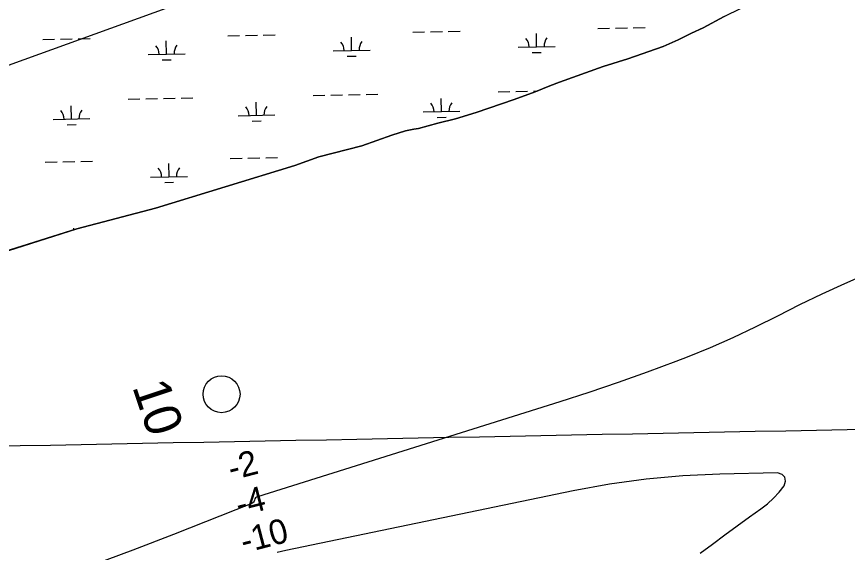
# Model space of a CAD drawing. Extents: x 3989314 to 4027622, y 243956 to 270014.
# Drawn here: x 3994901 to 3997154, y 255194 to 256648 of the extents above; entities that cross this region are included whole.
import ezdxf

# ---------------------------------------------------------------- set-up
doc = ezdxf.new("R2010")
doc.units = 0
for name, color, linetype in [('V-GRID-MAJR', 7, 'Continuous'), ('V-RIVR-EDGE', 7, 'Continuous'), ('V-RIVR-IDEN', 7, 'Continuous'), ('V-RIVR-MILE', 7, 'Continuous'), ('V-RIVR-RANG', 7, 'Continuous'), ('V-TOPO-MINR', 7, 'Continuous'), ('V-UTIL-LINE', 7, 'Continuous'), ('V-WETL-SWMP', 7, 'Continuous')]:
    doc.layers.add(name, color=color, linetype=linetype)

msp = doc.modelspace()

# ---------------------------------------------------------------- linework, layer by layer
at = {"layer": 'V-GRID-MAJR'}
msp.add_spline([(3993497.6, 255455.7), (3998815.3, 255559.8), (4004133, 255664.6), (4009450.7, 255770.2), (4014768.4, 255876.5), (4020086, 255983.7), (4025403.7, 256091.6)], degree=3, dxfattribs=at)
at = {"layer": 'V-RIVR-EDGE'}
msp.add_lwpolyline([(3994836.5, 255999.7), (3995064.6, 256071.4), (3995278, 256127.7), (3995655.8, 256243.8), (3995720.3, 256266.9), (3995837.6, 256297.4), (3995918.5, 256325.7), (3995955.7, 256337.7), (3995978.1, 256342.4), (3995990.7, 256344.3), (3996043.6, 256358.4), (3996091.8, 256370), (3996147.6, 256387), (3996250.8, 256422.5), (3996307.8, 256443.5), (3996346.8, 256459.8), (3996373.6, 256469.4), (3996492.1, 256512.3), (3996559, 256532.8), (3996654.2, 256566.6), (3996695, 256584.7), (3996731.4, 256602.8), (3996763.1, 256617.6), (3996820.4, 256647.6), (3996866.5, 256670.4)], dxfattribs=at)
at = {"layer": 'V-RIVR-MILE'}
msp.add_circle((3995456.9, 255622.8), 50, dxfattribs=at)
at = {"layer": 'V-TOPO-MINR'}
for points in [[(3997208.3, 255949.4), (3997146.5, 255922.7), (3997085.2, 255894.8), (3997024.6, 255865.4), (3996964.6, 255835), (3996904.4, 255804.7), (3996843.6, 255775.9), (3996781.9, 255749.2), (3996719.5, 255723.8), (3996689.3, 255712.1), (3996611.1, 255682.7), (3996532.6, 255654.4), (3996453.4, 255627.6), (3996374, 255601.8), (3995554, 255344.7), (3995551.2, 255343.2), (3995548.9, 255341.4), (3995547.4, 255338.8), (3995546.3, 255335.4), (3995545.3, 255332.6), (3995543.9, 255330.1), (3995541.8, 255328.2), (3995539.2, 255326.6), (3995326.4, 255242.5), (3995216.6, 255200.1), (3995106.4, 255159)], [(3996755.4, 255191.2), (3996788.6, 255216.2), (3996821.9, 255241), (3996855.4, 255265.5), (3996889.1, 255289.8), (3996920, 255312), (3996937.5, 255325.8), (3996954.1, 255340.7), (3996969.2, 255357.1), (3996983.2, 255374.5), (3996986.3, 255387.3), (3996985, 255397.9), (3996977.1, 255405), (3996964.8, 255409.8), (3996808.5, 255406.3), (3996708.2, 255401.3), (3996608.3, 255392.6), (3996509, 255378.5), (3996410.1, 255360.8), (3995631.1, 255198.8), (3995607.7, 255193.4)]]:
    msp.add_lwpolyline(points, dxfattribs=at)
at = {"layer": 'V-UTIL-LINE'}
msp.add_lwpolyline([(4011371.2, 261859.1), (4011335.1, 261835.4), (4010585.7, 261810.1), (4009561, 261669.6), (4009556.2, 261668.8), (4009323.1, 261637.1), (4006559.3, 260668.5), (4004279, 259872), (3996043.1, 256937.7), (3993486.8, 256012.2)], dxfattribs=at)
at = {"layer": 'V-WETL-SWMP'}
for p, q in [((3996820.4, 256647.6), (3996763.1, 256617.6)), ((3996525.5, 256616.5), (3996557.5, 256617.1)), ((3996573.5, 256617.4), (3996605.5, 256618)), ((3996763.1, 256617.6), (3996731.4, 256602.8)), ((3995473.9, 256595.5), (3995505.9, 256596.1)), ((3995521.9, 256596.5), (3995553.9, 256597.1)), ((3995569.8, 256597.4), (3995601.8, 256598)), ((3995975.7, 256605.5), (3996007.7, 256606.1)), ((3996023.7, 256606.5), (3996055.7, 256607.1)), ((3996071.7, 256607.4), (3996103.6, 256608)), ((3996311.4, 256565.7), (3996310.7, 256601.7)), ((3996477.5, 256615.5), (3996509.5, 256616.1)), ((3996731.4, 256602.8), (3996695, 256584.7)), ((3994972.1, 256585.5), (3995004.1, 256586.1)), ((3995020, 256586.5), (3995052, 256587.1)), ((3995068, 256587.4), (3995100, 256588)), ((3995307.8, 256545.7), (3995307, 256581.7)), ((3995809.6, 256555.7), (3995808.9, 256591.7)), ((3996695, 256584.7), (3996654.2, 256566.6)), ((3995759.6, 256554.8), (3995859.6, 256556.7)), ((3996261.4, 256564.8), (3996361.4, 256566.7)), ((3996299.7, 256550.1), (3996323.7, 256550.6)), ((3996654.2, 256566.6), (3996559, 256532.8)), ((3995257.8, 256544.8), (3995357.8, 256546.7)), ((3995296.1, 256530.1), (3995320.1, 256530.6)), ((3995797.9, 256540.1), (3995821.9, 256540.6)), ((3996559, 256532.8), (3996492.1, 256512.3)), ((3996492.1, 256512.3), (3996373.6, 256469.4)), ((3996346.8, 256459.8), (3996307.8, 256443.5)), ((3996373.6, 256469.4), (3996346.8, 256459.8)), ((3995849.1, 256436.4), (3995881.1, 256437.1)), ((3996206.9, 256443.6), (3996238.9, 256444.2)), ((3996307.8, 256443.5), (3996250.8, 256422.5)), ((3996254.9, 256444.5), (3996286.9, 256445.2)), ((3996302.9, 256445.5), (3996313, 256445.7)), ((3995203.3, 256423.6), (3995235.3, 256424.2)), ((3995251.3, 256424.5), (3995283.3, 256425.2)), ((3995299.3, 256425.5), (3995331.3, 256426.1)), ((3995347.3, 256426.4), (3995379.3, 256427.1)), ((3995551.6, 256379.8), (3995550.9, 256415.8)), ((3995705.1, 256433.6), (3995737.1, 256434.2)), ((3995753.1, 256434.5), (3995785.1, 256435.2)), ((3995801.1, 256435.5), (3995833.1, 256436.1)), ((3996053.4, 256389.8), (3996052.7, 256425.8)), ((3996250.8, 256422.5), (3996147.6, 256387)), ((3995049.8, 256369.8), (3995049.1, 256405.8)), ((3994999.8, 256368.8), (3995099.8, 256370.8)), ((3995501.6, 256378.8), (3995601.6, 256380.8)), ((3996003.4, 256388.8), (3996103.4, 256390.8)), ((3996041.7, 256374.1), (3996065.7, 256374.6)), ((3996091.8, 256370), (3996043.6, 256358.4)), ((3996147.6, 256387), (3996091.8, 256370)), ((3995038.1, 256354.1), (3995062.1, 256354.6)), ((3995539.9, 256364.1), (3995563.9, 256364.6)), ((3996043.6, 256358.4), (3995990.7, 256344.3)), ((3995918.5, 256325.7), (3995837.6, 256297.4)), ((3995955.7, 256337.7), (3995918.5, 256325.7)), ((3995978.1, 256342.4), (3995955.7, 256337.7)), ((3995990.7, 256344.3), (3995978.1, 256342.4)), ((3995837.6, 256297.4), (3995720.3, 256266.9)), ((3995480.5, 256262.9), (3995512.5, 256263.5)), ((3995528.5, 256263.8), (3995560.5, 256264.5)), ((3995576.5, 256264.8), (3995608.5, 256265.4)), ((3995720.3, 256266.9), (3995655.8, 256243.8)), ((3994978.7, 256252.9), (3995010.7, 256253.5)), ((3995026.7, 256253.8), (3995058.7, 256254.5)), ((3995074.7, 256254.8), (3995106.7, 256255.4)), ((3995655.8, 256243.8), (3995278, 256127.7)), ((3995314.4, 256213.1), (3995313.7, 256249.1)), ((3995264.4, 256212.1), (3995364.4, 256214.1)), ((3995302.7, 256197.5), (3995326.7, 256198)), ((3995278, 256127.7), (3995064.6, 256071.4)), ((3995064.6, 256071.4), (3994836.5, 255999.7)), ((3995055.8, 256068.7), (3995055.7, 256073.1))]:
    msp.add_line(p, q, dxfattribs=at)
for centre, start, end in [((3995754.3, 256555.1), 0.3699, 41.9135), ((3995864.8, 256557.3), 140.3699, 181.9135), ((3996256.1, 256565.1), 0.3699, 41.9135), ((3996366.6, 256567.3), 140.3699, 181.9135), ((3995252.5, 256545.1), 0.3699, 41.9135), ((3995363, 256547.3), 140.3699, 181.9135), ((3994994.5, 256369.1), 0.3699, 41.9135), ((3995105, 256371.3), 140.3699, 181.9135), ((3995496.3, 256379.1), 0.3699, 41.9135), ((3995606.8, 256381.3), 140.3699, 181.9135), ((3995998.2, 256389.1), 0.3699, 41.9135), ((3996108.6, 256391.3), 140.3699, 181.9135), ((3995259.1, 256212.5), 0.3699, 41.9135), ((3995369.6, 256214.7), 140.3699, 181.9135), ((3995001.2, 256036.5), 41.3702, 41.9135)]:
    msp.add_arc(centre, 35.2, start, end, dxfattribs=at)

# ---------------------------------------------------------------- texts
at = {"layer": 'V-RIVR-IDEN'}
msp.add_text('10', height=100, rotation=288.4167, dxfattribs=at).set_placement((3995214.1, 255643.4))
at = {"layer": 'V-RIVR-RANG'}
for s, p in [('-2', (3995483.6, 255388.4)), ('-4', (3995504.3, 255290.4)), ('-10', (3995517.5, 255190.8))]:
    msp.add_text(s, height=67, rotation=14.6049, dxfattribs=at).set_placement(p)

doc.saveas('drawing.dxf')
